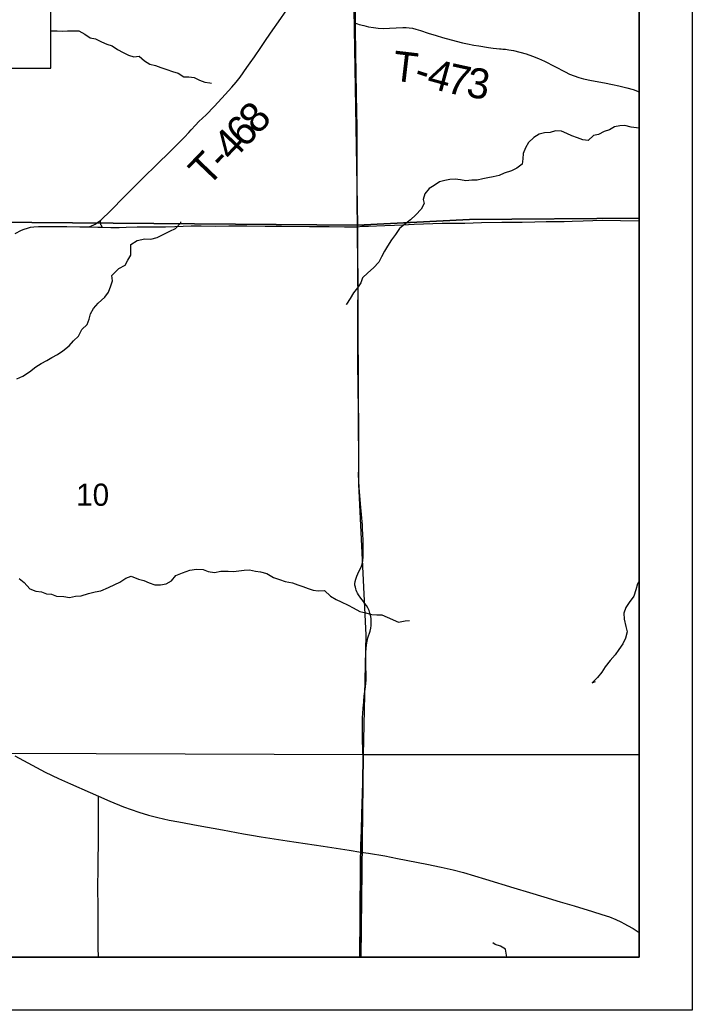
# Model space of a CAD drawing. Extents: x 0 to 34, y 0 to 22.
# Drawn here: x 7.49 to 8.76, y 14.287 to 16.159 of the extents above; entities that cross this region are included whole.
import ezdxf

# ---------------------------------------------------------------- set-up
doc = ezdxf.new("R2010")
doc.units = 0
for name, color, linetype in [('GM_X_County_Road', 7, 'Continuous'), ('GM_X_County_Road_Text', 7, 'Continuous'), ('GM_X_Interchange_Ramps', 7, 'Continuous'), ('GM_X_State_Location', 7, 'Continuous'), ('GM_X_State_Route', 7, 'Continuous'), ('GM_X_Township_Text', 7, 'Continuous'), ('SH_Data', 7, 'Continuous'), ('SH_Text', 7, 'Continuous')]:
    doc.layers.add(name, color=color, linetype=linetype)

msp = doc.modelspace()

# ---------------------------------------------------------------- linework, layer by layer
at = {"layer": 'GM_X_County_Road'}
for points in [[(7.4803, 14.7675), (7.513, 14.7498), (7.5295, 14.741), (7.5378, 14.7367), (7.5629, 14.7245), (7.5855, 14.7142), (7.6225, 14.6979), (7.6381, 14.6911)], [(7.6381, 14.6911), (7.6596, 14.6819), (7.6854, 14.6712), (7.7, 14.6657), (7.7147, 14.6607), (7.7326, 14.6554), (7.7507, 14.6507), (7.7719, 14.646), (7.7902, 14.6425), (7.8268, 14.6357), (7.8726, 14.6275), (7.9122, 14.62), (7.9275, 14.6173), (7.9459, 14.6142), (7.9951, 14.6068), (8.0627, 14.5966), (8.1118, 14.589), (8.1339, 14.5855)], [(8.1339, 14.5855), (8.1486, 14.5832), (8.1792, 14.5781), (8.2036, 14.5736), (8.2585, 14.5628), (8.2858, 14.557), (8.3086, 14.5519), (8.3283, 14.5466), (8.3697, 14.5342), (8.4232, 14.5179), (8.4529, 14.5088), (8.4797, 14.5007), (8.5107, 14.4916), (8.5372, 14.4837), (8.572, 14.4733), (8.5897, 14.4678), (8.6037, 14.4628), (8.6161, 14.4579), (8.6254, 14.4537), (8.6325, 14.4499), (8.6379, 14.447), (8.6487, 14.4409), (8.6602, 14.4336)]]:
    msp.add_lwpolyline(points, dxfattribs=at)
at = {"layer": 'GM_X_County_Road_Text'}
for points in [[(7.5483, 16.138), (7.5497, 16.1381), (7.5603, 16.1376), (7.5697, 16.1371), (7.58, 16.1378), (7.5906, 16.1381), (7.6012, 16.1376), (7.6125, 16.1314), (7.6223, 16.1249), (7.6329, 16.1225), (7.6439, 16.1171), (7.6541, 16.1129), (7.6643, 16.1094), (7.6744, 16.1028), (7.685, 16.0967), (7.6948, 16.092), (7.705, 16.0885), (7.7149, 16.0903), (7.7251, 16.0811), (7.7352, 16.075), (7.7458, 16.0722), (7.7564, 16.0683), (7.7674, 16.0648), (7.7783, 16.0613), (7.7889, 16.0578), (7.7995, 16.0512), (7.809, 16.0512), (7.8192, 16.0499), (7.8294, 16.0445), (7.8392, 16.0407), (7.849, 16.0398), (7.8517, 16.039)], [(8.6602, 15.954), (8.6549, 15.9544), (8.6447, 15.9556), (8.6329, 15.9588), (8.6235, 15.9581), (8.6136, 15.9563), (8.6037, 15.9507), (8.5938, 15.9474), (8.5835, 15.9422), (8.574, 15.9403), (8.5637, 15.9306), (8.5539, 15.9318), (8.5433, 15.9357), (8.5331, 15.9396), (8.5233, 15.9438), (8.5131, 15.9481), (8.5021, 15.9486), (8.4918, 15.946), (8.4812, 15.945), (8.471, 15.9424), (8.4607, 15.9364), (8.4507, 15.9267), (8.4454, 15.9169), (8.4407, 15.9063), (8.4399, 15.8961), (8.4387, 15.8858), (8.4287, 15.8783), (8.4185, 15.8731), (8.4052, 15.8691), (8.3957, 15.8646), (8.3843, 15.8617), (8.374, 15.8599), (8.3645, 15.8581), (8.3539, 15.8559), (8.3437, 15.8556), (8.3323, 15.8546), (8.3221, 15.8565), (8.3122, 15.8574), (8.3024, 15.8571), (8.2929, 15.8549), (8.2826, 15.8523), (8.2727, 15.8456), (8.2632, 15.84), (8.2547, 15.8298), (8.2516, 15.8193), (8.2535, 15.8115)], [(8.2535, 15.8115), (8.2479, 15.8009), (8.2378, 15.7902), (8.228, 15.7806), (8.2167, 15.7718), (8.2069, 15.7645), (8.1998, 15.7531), (8.1923, 15.7431), (8.1845, 15.7309), (8.1785, 15.7214), (8.1733, 15.7107), (8.1681, 15.7004), (8.1583, 15.6901), (8.1471, 15.6805), (8.1373, 15.671), (8.134, 15.6615), (8.128, 15.6519), (8.1201, 15.6424), (8.1142, 15.6317), (8.1067, 15.621), (8.1063, 15.6199)], [(7.4839, 15.48), (7.4952, 15.4854), (7.508, 15.4931), (7.5201, 15.5027), (7.5299, 15.5088), (7.5404, 15.5146), (7.5502, 15.5207), (7.5608, 15.5261), (7.5709, 15.5331), (7.5826, 15.5426), (7.5908, 15.5522), (7.6006, 15.561), (7.6066, 15.5732), (7.6171, 15.5828), (7.6204, 15.5927), (7.6233, 15.6029), (7.6286, 15.6128), (7.6376, 15.6232), (7.6503, 15.6346), (7.6571, 15.6442), (7.6619, 15.656), (7.6645, 15.6655), (7.6632, 15.6753), (7.6768, 15.6884), (7.6884, 15.6949), (7.694, 15.7044), (7.6993, 15.714), (7.6991, 15.7341), (7.7111, 15.7418), (7.7259, 15.7445), (7.7373, 15.7439), (7.749, 15.7474), (7.7607, 15.7532), (7.7731, 15.759), (7.7837, 15.7644), (7.7938, 15.7747), (7.7942, 15.777)], [(7.4885, 15.1025), (7.498, 15.095), (7.5087, 15.083), (7.5201, 15.0789), (7.5304, 15.0775), (7.5399, 15.0738), (7.5493, 15.0731), (7.5592, 15.0694), (7.5729, 15.0687), (7.5835, 15.0669), (7.5948, 15.0693), (7.6058, 15.0701), (7.6191, 15.0744), (7.6323, 15.0772), (7.6429, 15.0792), (7.6572, 15.0854), (7.6689, 15.0915), (7.6787, 15.0958), (7.69, 15.1035), (7.7002, 15.107), (7.7139, 15.1014), (7.7238, 15.0988), (7.7341, 15.0947), (7.7447, 15.0906), (7.7553, 15.0904), (7.7663, 15.0923), (7.7761, 15.0985), (7.7847, 15.1084), (7.7968, 15.1131), (7.8108, 15.1181), (7.8232, 15.1201), (7.8358, 15.1195), (7.8456, 15.1161), (7.8574, 15.1143), (7.8695, 15.1163), (7.8835, 15.1165), (7.8934, 15.1162), (7.9138, 15.1186), (7.9237, 15.1191), (7.9351, 15.1165), (7.9445, 15.1151), (7.9563, 15.1121)], [(7.9563, 15.1121), (7.9689, 15.1043), (7.9803, 15.101), (7.9909, 15.0969), (8.005, 15.0947), (8.0152, 15.0906), (8.0247, 15.0873), (8.0346, 15.0836), (8.0441, 15.0806), (8.0536, 15.0796), (8.0657, 15.0797), (8.0768, 15.0695), (8.0875, 15.0628), (8.097, 15.0583), (8.1099, 15.0523), (8.1198, 15.0475), (8.132, 15.0404), (8.1438, 15.0378), (8.1544, 15.0349), (8.1643, 15.0342), (8.1738, 15.0339), (8.184, 15.0294), (8.2053, 15.0198), (8.2178, 15.0225), (8.2258, 15.023)], [(8.6602, 15.0973), (8.6567, 15.0926), (8.6538, 15.0812), (8.6501, 15.0694), (8.6411, 15.0575), (8.6351, 15.0476), (8.6311, 15.0374), (8.6316, 15.026), (8.6347, 15.012), (8.6371, 15.0021), (8.6342, 14.9896), (8.6293, 14.9793), (8.6218, 14.9686), (8.6144, 14.9583), (8.6054, 14.9476), (8.596, 14.9358), (8.5893, 14.9258), (8.581, 14.9155), (8.5713, 14.9052), (8.5777, 14.9079)], [(8.4099, 14.3866), (8.4096, 14.3909), (8.4076, 14.4019), (8.3981, 14.4075), (8.3882, 14.4105), (8.3832, 14.4142)]]:
    msp.add_lwpolyline(points, dxfattribs=at)
at = {"layer": 'GM_X_Interchange_Ramps'}
for points in [[(7.9251, 16.0776), (7.9328, 16.0886), (7.9449, 16.1065), (7.9554, 16.1218), (7.9678, 16.1396), (7.9783, 16.155), (7.9943, 16.1777), (8.0018, 16.1876), (8.0095, 16.1973), (8.0214, 16.2115), (8.0356, 16.2279), (8.0477, 16.242), (8.0559, 16.2513), (8.0601, 16.2558), (8.0646, 16.26), (8.0694, 16.2639), (8.0719, 16.2657), (8.0764, 16.2691)], [(8.1239, 16.1521), (8.1237, 16.1709), (8.1239, 16.1802), (8.1239, 16.1832), (8.1235, 16.1956), (8.1226, 16.236), (8.1221, 16.2599)], [(8.1277, 15.7676), (8.1277, 15.7692), (8.1272, 15.8112), (8.1271, 15.8299), (8.1269, 15.8485), (8.1271, 15.8714), (8.1274, 15.9013), (8.1274, 15.925), (8.1274, 15.9403), (8.1274, 15.954), (8.1266, 15.988), (8.1259, 16.0158), (8.1257, 16.0321), (8.1255, 16.0452), (8.1253, 16.0655), (8.1249, 16.0872), (8.1245, 16.1089), (8.1241, 16.1306), (8.1239, 16.1521)], [(8.1239, 16.1521), (8.1277, 16.151), (8.1306, 16.1501), (8.1396, 16.1477), (8.1486, 16.1456), (8.1577, 16.144), (8.1669, 16.143), (8.1762, 16.1426), (8.1885, 16.1428), (8.2009, 16.1434), (8.2133, 16.1442), (8.2195, 16.1442), (8.2256, 16.1437), (8.2318, 16.1427), (8.2378, 16.1413), (8.2467, 16.1384), (8.2614, 16.1333), (8.2763, 16.1289), (8.2885, 16.1253), (8.3145, 16.1185), (8.3264, 16.1153), (8.3355, 16.1133), (8.3477, 16.111), (8.3568, 16.1094), (8.3752, 16.1066), (8.3843, 16.1053), (8.3903, 16.1045), (8.3963, 16.1039), (8.3992, 16.1037), (8.4021, 16.1034), (8.4077, 16.103), (8.4136, 16.1021), (8.4227, 16.1005), (8.4348, 16.0977), (8.4468, 16.0943), (8.4586, 16.0903), (8.4701, 16.0856), (8.4813, 16.0803), (8.5006, 16.0702), (8.5199, 16.0601), (8.5283, 16.0561), (8.5369, 16.0526), (8.5458, 16.0497), (8.5547, 16.0472), (8.5699, 16.0438), (8.5943, 16.0393), (8.6096, 16.0366), (8.6217, 16.0341), (8.6367, 16.0303), (8.6485, 16.0268), (8.6602, 16.0228)], [(7.6426, 15.78), (7.6467, 15.7837), (7.658, 15.7947), (7.6907, 15.8278), (7.7082, 15.8454), (7.7213, 15.8586), (7.7501, 15.8868), (7.7723, 15.9085), (7.79, 15.9259), (7.8006, 15.937), (7.8092, 15.9459), (7.8133, 15.9505), (7.8218, 15.9597), (7.8282, 15.9663), (7.8415, 15.9794), (7.8567, 15.9949), (7.8716, 16.0107), (7.8904, 16.0314), (7.8984, 16.0408), (7.906, 16.0506), (7.9185, 16.0683), (7.9251, 16.0776)], [(7.4811, 15.7547), (7.4925, 15.7609), (7.4981, 15.7632), (7.504, 15.7652), (7.5101, 15.7667), (7.5162, 15.7676), (7.5252, 15.7681), (7.5533, 15.7681), (7.5784, 15.7679), (7.6028, 15.7674), (7.6177, 15.7671)], [(7.6177, 15.7671), (7.6219, 15.7682), (7.6251, 15.7693), (7.6293, 15.7711), (7.6321, 15.7726), (7.6345, 15.7741), (7.639, 15.7774), (7.6426, 15.78)], [(7.6177, 15.7671), (7.6368, 15.7668), (7.6455, 15.7665)], [(7.6455, 15.7665), (7.6443, 15.7684), (7.6437, 15.7698), (7.643, 15.7714), (7.6426, 15.7728), (7.6423, 15.7746), (7.6421, 15.7766), (7.6421, 15.7776), (7.6422, 15.7785), (7.6425, 15.7794), (7.6426, 15.78)], [(7.6455, 15.7665), (7.6616, 15.766), (7.6772, 15.7662), (7.6905, 15.7666), (7.7112, 15.7672), (7.7267, 15.7674), (7.7422, 15.7674), (7.7652, 15.7675), (7.7826, 15.7679), (7.798, 15.7685), (7.8135, 15.769), (7.8322, 15.769), (7.8599, 15.7688), (7.8847, 15.769), (7.9002, 15.7691), (7.9189, 15.7692), (7.953, 15.7689), (7.9841, 15.7688), (8.0368, 15.7682), (8.0741, 15.7681), (8.1032, 15.7675), (8.1245, 15.7673), (8.1277, 15.7676)], [(8.144, 14.9174), (8.1439, 14.9214), (8.1438, 14.9363), (8.1432, 14.9473), (8.1432, 14.9506), (8.1433, 14.9564), (8.1436, 14.9635), (8.1441, 14.9704), (8.1447, 14.9769), (8.146, 14.9839), (8.1476, 14.9907), (8.1517, 15.0034), (8.1529, 15.0087), (8.1536, 15.0139), (8.1538, 15.0203), (8.1535, 15.0268), (8.1521, 15.0331), (8.1511, 15.0371), (8.1495, 15.0423), (8.1472, 15.0469), (8.1447, 15.0514), (8.1416, 15.0557), (8.139, 15.0593), (8.134, 15.0654), (8.1297, 15.0718), (8.1277, 15.0752), (8.1265, 15.0775), (8.1255, 15.0803), (8.1246, 15.0833), (8.1237, 15.0865), (8.123, 15.09), (8.1228, 15.0928), (8.1234, 15.0971), (8.1246, 15.1013), (8.1264, 15.1069), (8.1303, 15.1157), (8.1344, 15.124), (8.1364, 15.1299), (8.1371, 15.1328), (8.1376, 15.1356), (8.1383, 15.1447), (8.1382, 15.151), (8.1383, 15.1675), (8.1382, 15.1762), (8.138, 15.1849), (8.1378, 15.1887), (8.1375, 15.1936), (8.1371, 15.2033), (8.1337, 15.2435), (8.131, 15.2745), (8.1303, 15.2868), (8.1299, 15.2992), (8.13, 15.3085), (8.1302, 15.3209), (8.1304, 15.3427), (8.1303, 15.3738), (8.1301, 15.4049), (8.1299, 15.4267), (8.1293, 15.4578), (8.1289, 15.4764), (8.1287, 15.4981), (8.1285, 15.526), (8.1285, 15.5571), (8.1283, 15.5788), (8.1287, 15.6192), (8.1288, 15.641), (8.1284, 15.669), (8.1281, 15.7094), (8.1277, 15.7436), (8.1277, 15.7676)], [(8.1277, 15.7676), (8.1359, 15.7684), (8.1483, 15.7687), (8.1792, 15.7699), (8.1978, 15.7707), (8.2133, 15.7714), (8.2348, 15.7724), (8.2876, 15.7742), (8.3058, 15.7746), (8.3304, 15.7746), (8.3624, 15.7755), (8.4004, 15.776), (8.4389, 15.7762), (8.463, 15.7769), (8.4841, 15.7773), (8.5181, 15.7776), (8.5336, 15.778), (8.5545, 15.779), (8.5906, 15.7799), (8.6247, 15.7796), (8.6602, 15.7786)], [(8.1339, 14.5855), (8.1342, 14.5981), (8.1352, 14.6261), (8.1362, 14.6571), (8.138, 14.7162), (8.1386, 14.7442), (8.1384, 14.7628), (8.1373, 14.797), (8.1371, 14.8156), (8.1374, 14.8385), (8.1378, 14.8488), (8.1385, 14.856), (8.1387, 14.8588), (8.1389, 14.8618), (8.1397, 14.8708), (8.1406, 14.8801), (8.1429, 14.898), (8.1441, 14.9114), (8.144, 14.9174)], [(7.6383, 14.3866), (7.6379, 14.4049), (7.6376, 14.4546), (7.6376, 14.4702), (7.6377, 14.4857), (7.6373, 14.5135), (7.6373, 14.529), (7.6374, 14.5445), (7.6378, 14.5694), (7.6378, 14.5787), (7.6379, 14.5818), (7.638, 14.5911), (7.638, 14.5981), (7.6381, 14.6081), (7.6381, 14.6208), (7.6382, 14.6323), (7.6382, 14.6431), (7.6383, 14.653), (7.6383, 14.6619), (7.6383, 14.668), (7.6383, 14.6729), (7.6383, 14.6779), (7.6382, 14.6834), (7.6381, 14.6903), (7.6381, 14.6911)], [(8.132, 14.3866), (8.132, 14.3867), (8.1322, 14.4116), (8.1325, 14.4395), (8.133, 14.4955), (8.1333, 14.5297), (8.1337, 14.5763), (8.1339, 14.5855)]]:
    msp.add_lwpolyline(points, dxfattribs=at)
at = {"layer": 'GM_X_State_Route'}
for points in [[(8.6602, 15.784), (8.6602, 16.7776), (8.1109, 16.7736), (8.1275, 15.7704), (8.3397, 15.7814)], [(8.6602, 14.7699), (8.6602, 15.784), (8.3397, 15.7814), (8.1275, 15.7704), (8.1296, 15.2812), (8.1434, 14.9958), (8.1382, 14.7696)], [(7.1266, 15.779), (8.1275, 15.7704), (8.1296, 15.2812), (8.1434, 14.9958), (8.1382, 14.7696), (7.1286, 14.7729)], [(7.1397, 14.3866), (8.1341, 14.3866), (8.1382, 14.7696), (7.1286, 14.7729)], [(8.1341, 14.3866), (8.6602, 14.3866), (8.6602, 14.7699), (8.1382, 14.7696)]]:
    msp.add_lwpolyline(points, close=True, dxfattribs=at)
msp.add_lwpolyline([(7.5483, 16.7695), (8.1109, 16.7736), (8.1275, 15.7704), (7.1266, 15.779), (7.1265, 15.7834), (7.124, 16.0674)], dxfattribs=at)
at = {"layer": 'SH_Data'}
for points in [[(1.7602, 21.2866), (8.7602, 21.2866), (8.7602, 14.2866), (1.7602, 14.2866)], [(1.8602, 21.1866), (8.6602, 21.1866), (8.6602, 14.3866), (1.8602, 14.3866)]]:
    msp.add_lwpolyline(points, close=True, dxfattribs=at)
at = {"layer": 'SH_Text'}
for p, q in [((7.5483, 16.0674), (7.5483, 16.8504)), ((5.4199, 16.0674), (7.5483, 16.0674))]:
    msp.add_line(p, q, dxfattribs=at)

# ---------------------------------------------------------------- texts
at = {"layer": 'GM_X_State_Location'}
msp.add_text('10', height=0.04186, rotation=0, dxfattribs=at).set_placement((7.5961, 15.2401))
at = {"layer": 'GM_X_Township_Text'}
for s, rotation, p in [('T', 353.3034, (8.192, 16.0442)), ('-', 342.1328, (8.2314, 16.0399)), ('4', 344.6523, (8.2562, 16.032)), ('7', 347.6128, (8.2931, 16.0219)), ('3', 351.5567, (8.3314, 16.0137)), ('8', 46.6959, (7.9392, 15.94)), ('6', 46.3575, (7.9147, 15.9144)), ('4', 46.2634, (7.8905, 15.889)), ('T', 46.2274, (7.8449, 15.8415)), ('-', 46.2144, (7.8743, 15.8721))]:
    msp.add_text(s, height=0.0568, rotation=rotation, dxfattribs=at).set_placement(p)

doc.saveas('drawing.dxf')
